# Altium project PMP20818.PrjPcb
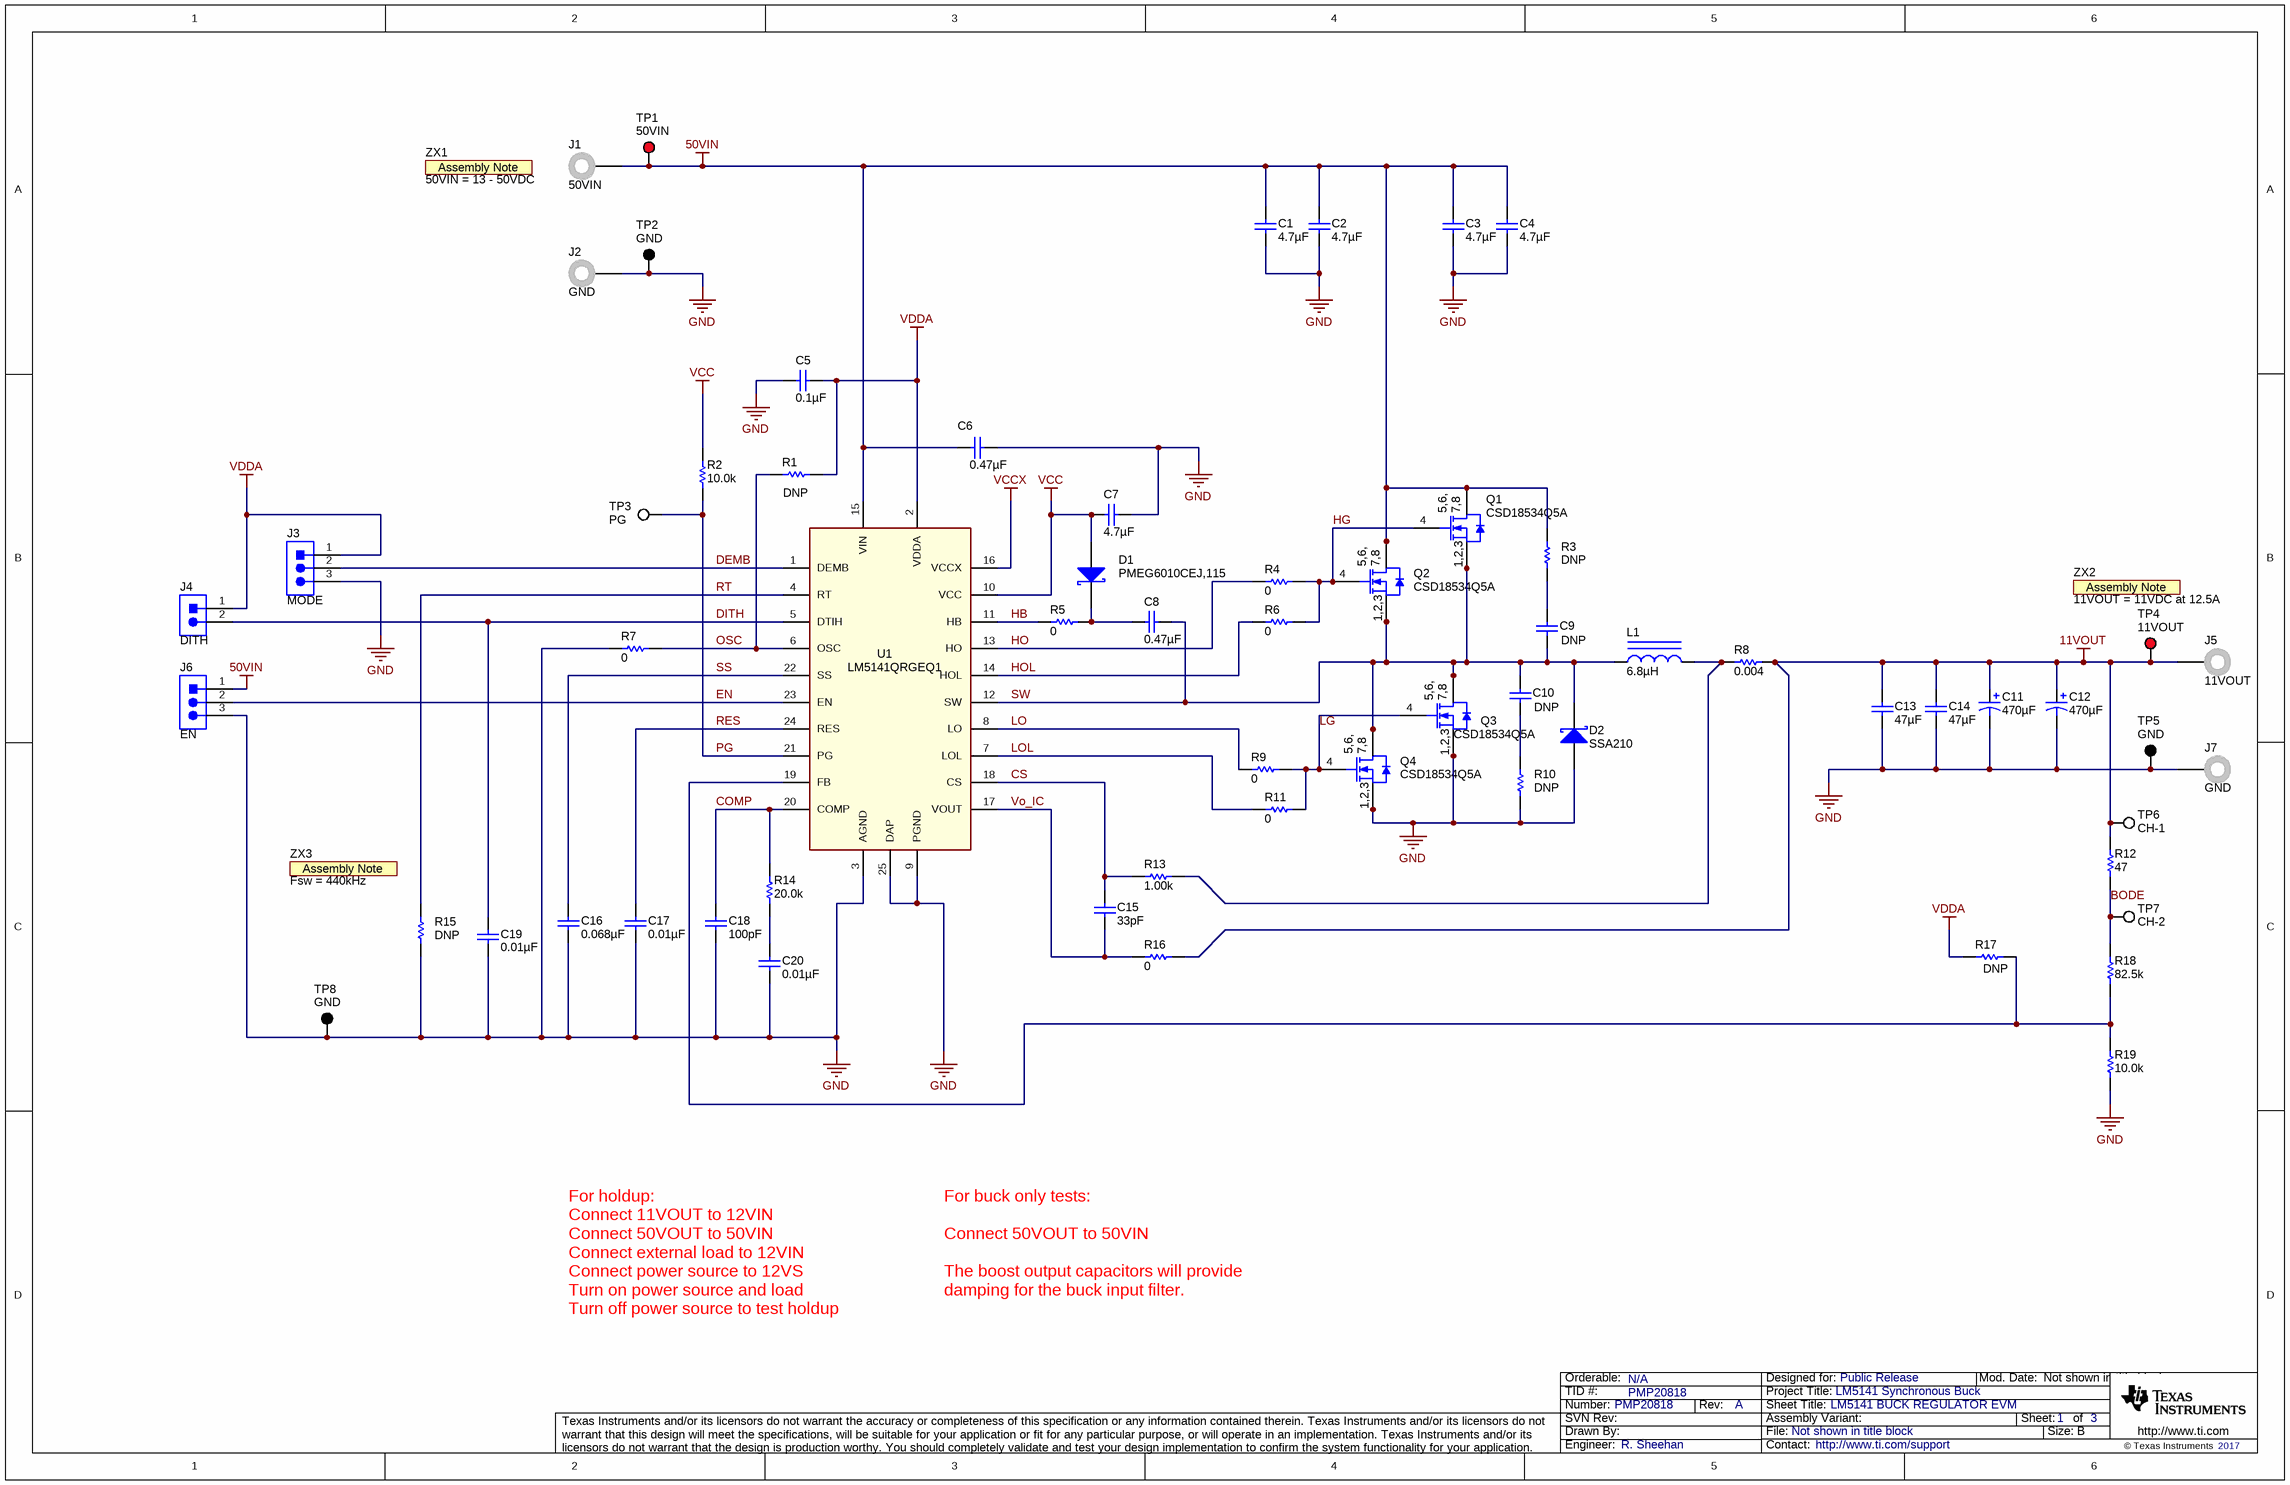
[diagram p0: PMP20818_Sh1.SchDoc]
CopyrightYear: 2017; EVM_Orderable: N/A; PCB_Layout: H. Kasparian; PCB_Rev: A; PRJ_Customer: Public Release; PRJ_Engineer: R. Sheehan; PRJ_Number: PMP20818; PRJ_Title: LM5141 Synchronous Buck; SCH_Rev: A; TechSupport: http://www.ti.com/support; TID: PMP20818
3 sheets, 134 parts. Net scope: global (net labels, ports and power ports of the same name join across sheets).
Board file: PMP20818.PcbDoc
Sheets:
  PMP20818_Sh1.SchDoc
  PMP20818_Sh2.SchDoc
  PMP20818_Sh3.SchDoc

## Sheet PMP20818_Sh1.SchDoc: LM5141 BUCK REGULATOR EVM
size 431 x 279 mm; Date: Not shown in title block; ApprovedBy: Not shown in title block; CheckedBy: Not shown in title block; Author: Not shown in title block; CompanyName: Not shown in title block; Engineer: Not shown in title block; Organization: Not shown in title block; Address1: Not shown in title block; Address2: Not shown in title block; Address3: Not shown in title block; Address4: Not shown in title block; DocumentNumber: 1; Revision: Use project parameter SCH_Rev; SheetNumber: 1; SheetTotal: 3; PageSetup: Record=PageOptions¦CenterHorizontal=True¦CenterVertical=True¦PrintScale=0.96¦XCorrection=1.00¦YCorrection=1.00¦PrintKind=0¦BorderSize=5000000¦LeftOffset=0¦BottomOffset=0¦Orientation=2¦PaperLength=1000¦PaperWidth=1000¦Scale=100¦PaperSource=15¦PrintQuality=-3¦MediaType=1¦DitherType=10¦PrintScaleMode=1¦PaperKind=11x17¦PaperIndex=17

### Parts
C1  ValueDisplayed: 4.7µF  [1206_190]  (hidden comment: UMK316AB7475KL-T)
C2  ValueDisplayed: 4.7µF  [1206_190]  (hidden comment: UMK316AB7475KL-T)
C3  ValueDisplayed: 4.7µF  [1206_190]  (hidden comment: UMK316AB7475KL-T)
C4  ValueDisplayed: 4.7µF  [1206_190]  (hidden comment: UMK316AB7475KL-T)
C5  ValueDisplayed: 0.1µF  [0603]  (hidden comment: C0603C104K5RACTU)
C6  ValueDisplayed: 0.47µF  [0805L]  (hidden comment: GRM21BR72A474KA73L)
C7  ValueDisplayed: 4.7µF  [0603]  (hidden comment: GRM188R61C475KAAJ)
C8  ValueDisplayed: 0.47µF  [0603]  (hidden comment: CGA3E3X7R1H474K080AB)
C9  DNP  [0603]
C10  DNP  [0603]
C11  ValueDisplayed: 470µF  [CAPSMT_62_JC0]  (hidden comment: 16SVPE470M)
C12  ValueDisplayed: 470µF  [CAPSMT_62_JC0]  (hidden comment: 16SVPE470M)
C13  ValueDisplayed: 47µF  [2220_250]  (hidden comment: CGA9N3X7R1C476M230KB)
C14  ValueDisplayed: 47µF  [2220_250]  (hidden comment: CGA9N3X7R1C476M230KB)
C15  ValueDisplayed: 33pF  [0603]  (hidden comment: 06035A330JAT2A)
C16  ValueDisplayed: 0.068µF  [0603]  (hidden comment: GRM188R71E683KA01D)
C17  ValueDisplayed: 0.01µF  [0603]  (hidden comment: C1608X7R2A103M)
C18  ValueDisplayed: 100pF  [0603]  (hidden comment: GRM1885C1H101JA01D)
C19  ValueDisplayed: 0.01µF  [0603]  (hidden comment: C1608X7R2A103M)
C20  ValueDisplayed: 0.01µF  [0603]  (hidden comment: GRM188R71E103KA01D)
D1  PMEG6010CEJ,115  [SOD-323F]
D2  SSA210  [SMA]
J1  50VIN  [Keystone_575-4]
J2  GND  [Keystone_575-4]
J3  MODE  [WURTH_61300311121]
J4  DITH  [WURTH_61300211121]
J5  11VOUT  [Keystone_575-4]
J6  EN  [WURTH_61300311121]
J7  GND  [Keystone_575-4]
L1  ValueDisplayed: 6.8µH  [XAL1510]  (hidden comment: XAL1510-682MEB)
Q1  CSD18534Q5A  [DQJ0008A]
Q2  CSD18534Q5A  [DQJ0008A]
Q3  CSD18534Q5A  [DQJ0008A]
Q4  CSD18534Q5A  [DQJ0008A]
R1  DNP  [0603]
R2  ValueDisplayed: 10.0k  [0603]  (hidden comment: CRCW060310K0FKEA)
R3  DNP  [1206]
R4  ValueDisplayed: 0  [0603S]  (hidden comment: CRCW06030000Z0EA)
R5  ValueDisplayed: 0  [0603S]  (hidden comment: CRCW06030000Z0EA)
R6  ValueDisplayed: 0  [0603S]  (hidden comment: CRCW06030000Z0EA)
R7  ValueDisplayed: 0  [0603]  (hidden comment: CRCW06030000Z0EA)
R8  ValueDisplayed: 0.004  [2512_WIDE]  (hidden comment: KRL6432E-M-R004-F-T1)
R9  ValueDisplayed: 0  [0603S]  (hidden comment: CRCW06030000Z0EA)
R10  DNP  [1206]
R11  ValueDisplayed: 0  [0603S]  (hidden comment: CRCW06030000Z0EA)
R12  ValueDisplayed: 47  [0603]  (hidden comment: CRCW060347R0JNEA)
R13  ValueDisplayed: 1.00k  [0603]  (hidden comment: CRCW06031K00FKEA)
R14  ValueDisplayed: 20.0k  [0603]  (hidden comment: CRCW060320K0FKEA)
R15  DNP  [0603]
R16  ValueDisplayed: 0  [0603]  (hidden comment: CRCW06030000Z0EA)
R17  DNP  [0603]
R18  ValueDisplayed: 82.5k  [0603]  (hidden comment: CRCW060382K5FKEA)
R19  ValueDisplayed: 10.0k  [0603]  (hidden comment: CRCW060310K0FKEA)
TP1  50VIN  [Keystone5010]
TP2  GND  [Keystone5011]
TP3  PG  [Keystone5012]
TP4  11VOUT  [Keystone5010]
TP5  GND  [Keystone5011]
TP6  CH-1  [Keystone5012]
TP7  CH-2  [Keystone5012]
TP8  GND  [Keystone5011]
U1  LM5141QRGEQ1  [RGE0024H]
ZX1  50VIN = 13 - 50VDC  [AssemblyNote]  (no BOM)
ZX2  11VOUT = 11VDC at 12.5A  [AssemblyNote]  (no BOM)
ZX3  Fsw = 440kHz  [AssemblyNote]  (no BOM)

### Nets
11VOUT: C11.1(+) C12.1(+) C13.1 C14.1 J5.1 R8.2 R12.2 R16.2 TP4.1 TP6.1
50VIN: C1.1 C2.1 C3.1 C4.1 C6.2 J1.1 J6.1 Q1.5(D) Q1.6(D) Q1.7(D) Q1.8(D) Q1.9(D) Q2.5(D) Q2.6(D) Q2.7(D) Q2.8(D) Q2.9(D) R3.2 TP1.1 U1.15(VIN)
GND: C1.2 C2.2 C3.2 C4.2 C5.1 C6.1 C7.1 C11.2(-) C12.2(-) C13.2 C14.2 C16.2 C17.2 C18.2 C19.2 C20.2 D2.2(A) J2.1 J3.3 J6.3 J7.1 Q3.1(S) Q3.2(S) Q3.3(S) Q4.1(S) Q4.2(S) Q4.3(S) R7.2 R10.1 R15.1 R19.1 TP2.1 TP5.1 TP8.1 U1.3(AGND) U1.9(PGND) U1.25(DAP)
VCC: C7.2 D1.2(A) R2.1 U1.10(VCC)
VCCX: U1.16(VCCX)
VDDA: C5.2 J3.1 J4.1 R1.1 R17.1 U1.2(VDDA)
BODE: R12.1 R18.2 TP7.1
COMP: C18.1 R14.2 U1.20(COMP)
CS: C15.2 R13.1 U1.18(CS)
DEMB: J3.2 U1.1(DEMB)
DITH: C19.1 J4.2 U1.5(DTIH)
EN: J6.2 U1.23(EN)
HB: R5.1 U1.11(HB)
HG: Q1.4(G) Q2.4(G) R4.2 R6.1
HO: R4.1 U1.13(HO)
HOL: R6.2 U1.14(HOL)
LG: Q3.4(G) Q4.4(G) R9.2 R11.1
LO: R9.1 U1.8(LO)
LOL: R11.2 U1.7(LOL)
OSC: R1.2 R7.1 U1.6(OSC)
PG: R2.2 TP3.1 U1.21(PG)
RES: C17.1 U1.24(RES)
RT: R15.2 U1.4(RT)
SS: C16.1 U1.22(SS)
SW: C8.2 C9.2 C10.1 D2.1(K) L1.1 Q1.1(S) Q1.2(S) Q1.3(S) Q2.1(S) Q2.2(S) Q2.3(S) Q3.5(D) Q3.6(D) Q3.7(D) Q3.8(D) Q3.9(D) Q4.5(D) Q4.6(D) Q4.7(D) Q4.8(D) Q4.9(D) U1.12(SW)
Vo_IC: C15.1 R16.1 U1.17(VOUT)
NetC8_1: C8.1 D1.1(K) R5.2
NetC9_1: C9.1 R3.1
NetC10_2: C10.2 R10.2
NetC20_1: C20.1 R14.1
NetL1_2: L1.2 R8.1 R13.2
NetR17_2: R17.2 R18.1 R19.2 U1.19(FB)

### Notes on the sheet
- For holdup:
  Connect 11VOUT to 12VIN
  Connect 50VOUT to 50VIN
  Connect external load to 12VIN
  Connect power source to 12VS
  Turn on power source and load
  Turn off power source to test holdup
- For buck only tests:
  Connect 50VOUT to 50VIN
  The boost output capacitors will provide damping for the buck input filter.

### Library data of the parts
C1-C4 = UMK316AB7475KL-T: CAP, CERM, 4.7 µF, 50 V, +/- 10%, X7R, 1206_190; Manufacturer: Taiyo Yuden; Polarized: N; CompType: Capacitor; Value: 4.7uF; U/M: EA; Cap_F: 0.0000047; Tolerance_%: 10; Value1: Unknown; VDC_V: 50; Value2: 50V; TaMin_C: -55; TaMax_C: 125; Cap_Case: 1206; SizeArea_mm2: 5.12; SizeAreaWB_mm2: 10.92; SizeX_mm: 3.2; SizeY_mm: 1.6; SizeZ_mm: 1.9; AEC Category: Q200
C5 = C0603C104K5RACTU: CAP, CERM, 0.1 µF, 50 V, +/- 10%, X7R, 0603; Manufacturer: Kemet; Polarized: N; CompType: Capacitor; Value: 0.1uF; U/M: EA; Cap_F: 0.0000001; Tolerance_%: 10; Value1: Unknown; VDC_V: 50; Value2: 50V; TaMin_C: -55; TaMax_C: 125
C6 = GRM21BR72A474KA73L: CAP, CERM, 0.47 µF, 100 V, +/- 10%, X7R, 0805; Manufacturer: MuRata; Polarized: N; CompType: Capacitor; Value: 0.47uF; U/M: EA; Cap_F: 0.00000047; Tolerance_%: 10; Value1: Unknown; VDC_V: 100; Value2: 100V; TaMin_C: -55; TaMax_C: 125; Cap_Case: 0805
C7 = GRM188R61C475KAAJ: CAP, CERM, 4.7 µF, 16 V, +/- 10%, X5R, 0603; Manufacturer: MuRata; Polarized: N; CompType: Capacitor; Value: 4.7uF; U/M: EA; Cap_F: 0.0000047; Tolerance_%: 10; Value1: Unknown; VDC_V: 16; Value2: 16V; TaMin_C: -55; TaMax_C: 85
C8 = CGA3E3X7R1H474K080AB: CAP, CERM, 0.47 µF, 50 V, +/- 10%, X7R, AEC-Q200 Grade 1, 0603; Manufacturer: TDK; Polarized: N; CompType: Capacitor; Value: 0.47uF; U/M: EA; Cap_F: 0.00000047; Tolerance_%: 10; ESR_ohm: 0.01064; Value1: 0.01064 ohm; VDC_V: 50; Value2: 50V; IRMS_A: 1.59966; TaMin_C: -55; TaMax_C: 125; SizeArea_mm2: 1.28; SizeAreaWB_mm2: 4.68; SizeX_mm: 1.6; SizeY_mm: 0.8; SizeZ_mm: 1; AEC Category: Q200; AEC Qualified: Y
C9 C10 = GRM1885C2A102JA01D: CAP, CERM, 1000 pF, 100 V, +/- 5%, C0G/NP0, 0603; Manufacturer: MuRata; Polarized: N; CompType: Capacitor; Value: 1000pF; U/M: EA; Cap_F: 0.000000001; Tolerance_%: 5; Value1: Unknown; VDC_V: 100; Value2: 100V; TaMin_C: -55; TaMax_C: 125
C11 C12 = 16SVPE470M: CAP, Aluminum Polymer, 470 µF, 16 V, +/- 20%, 0.01 ohm, JC0 SMD; Manufacturer: Panasonic; Polarized: Y; CompType: Capacitor; Value: 470uF; U/M: EA; Cap_F: 0.00047; Tolerance_%: 20; VDC_V: 16; Value2: 16V; ESR_ohm: 0.01; IRMS_A: 6.1; TaMin_C: -55; TaMax_C: 105; AEC Category: Q200; SizeAreaWB_mm2: 156.25; SizeArea_mm2: 110.25; SizeX_mm: 10.5; SizeZ_mm: 12.5
C13 C14 = CGA9N3X7R1C476M230KB: CAP, CERM, 47 µF, 16 V, +/- 20%, X7R, AEC-Q200 Grade 1,; Manufacturer: TDK; Polarized: N; CompType: Capacitor; Value: 47uF; U/M: EA; Cap_F: 0.000047; Tolerance_%: 20; ESR_ohm: 0.003162; Value1: 0.003162 ohm; VDC_V: 16; Value2: 16V; IRMS_A: 5.13436; TaMin_C: -55; TaMax_C: 125; SizeArea_mm2: 28.5; SizeAreaWB_mm2: 53.9; SizeX_mm: 5.7; SizeY_mm: 5; SizeZ_mm: 2.5; AEC Category: Q200; AEC Qualified: Y; AEC Grade: 1
C15 = 06035A330JAT2A: CAP, CERM, 33 pF, 50 V, +/- 5%, C0G/NP0, 0603; Manufacturer: AVX; Polarized: N; CompType: Capacitor; Value: 33pF; U/M: EA; Cap_F: 0.000000000033; Tolerance_%: 5; ESR_ohm: 0.209; Value1: 0.209 ohm; VDC_V: 50; Value2: 50V; TaMin_C: -55; TaMax_C: 125
C16 = GRM188R71E683KA01D: CAP, CERM, 0.068 µF, 25 V, +/- 10%, X7R, 0603; Manufacturer: MuRata; Polarized: N; CompType: Capacitor; Value: 0.068uF; U/M: EA; Cap_F: 0.000000068; Tolerance_%: 10; Value1: Unknown; VDC_V: 25; Value2: 25V; TaMin_C: -55; TaMax_C: 125
C17 C19 = C1608X7R2A103M: CAP, CERM, 0.01 µF, 100 V, +/- 20%, X7R, 0603; Manufacturer: TDK; Polarized: N; CompType: Capacitor; Value: 0.01uF; U/M: EA; Cap_F: 0.00000001; Tolerance_%: 20; ESR_ohm: 0.0661; Value1: 0.0661 ohm; VDC_V: 100; Value2: 100V; TaMin_C: -55; TaMax_C: 125
C18 = GRM1885C1H101JA01D: CAP, CERM, 100 pF, 50 V, +/- 5%, C0G/NP0, 0603; Manufacturer: MuRata; Polarized: N; CompType: Capacitor; Value: 100pF; U/M: EA; Cap_F: 0.0000000001; Tolerance_%: 5; Value1: Unknown; VDC_V: 50; Value2: 50V; TaMin_C: -55; TaMax_C: 125; SizeArea_mm2: 1.28; SizeAreaWB_mm2: 4.68; SizeX_mm: 1.6; SizeY_mm: 0.8; SizeZ_mm: 1; AEC Category: Q200
C20 = GRM188R71E103KA01D: CAP, CERM, 0.01 µF, 25 V, +/- 10%, X7R, 0603; Manufacturer: MuRata; Polarized: N; CompType: Capacitor; Value: 0.01uF; U/M: EA; Cap_F: 0.00000001; Tolerance_%: 10; Value1: Unknown; VDC_V: 25; Value2: 25V; TaMin_C: -55; TaMax_C: 125; SizeArea_mm2: 1.28; SizeAreaWB_mm2: 4.68; SizeX_mm: 1.6; SizeY_mm: 0.8; SizeZ_mm: 1; AEC Category: Q200
D1 = PMEG6010CEJ,115: Diode, Schottky, 60 V, 1 A, SOD-323F; Manufacturer: NXP Semiconductor; U/M: EA; Vf_V: 0.66; Value: 60V; Value1: 1A; Value2: 0.66V; Io_A: 1; Vr_V: 60; TJmax_C: 150
D2 = SSA210: Diode, Schottky, 100 V, 2 A, AEC-Q101, SMA; Manufacturer: Fairchild Semiconductor; U/M: EA; Vf_V: 0.8; Value: 100V; Value1: 2A; Value2: 0.8V; Io_A: 2; Vr_V: 100; TJmax_C: 175; SizeAreaWB_mm2: 37.3428; SizeArea_mm2: 16.3228; SizeX_mm: 5.59; SizeY_mm: 2.92; SizeZ_mm: 2.87; AEC Category: Q101; AEC Qualified: Y
J1 J2 J5 J7 = 575-4: Standard Banana Jack, Uninsulated, 5.5mm; Manufacturer: Keystone; CompType: Connector
J3 J6 = 61300311121: Header, 2.54 mm, 3x1, Gold, TH; Manufacturer: Wurth Elektronik; SymbolCreator: a0799628
J4 = 61300211121: Header, 2.54 mm, 2x1, Gold, TH; Manufacturer: Wurth Elektronik; SymbolCreator: a0412235
L1 = XAL1510-682MEB: Inductor, Shielded, Composite, 6.8 µH, 26 A, 0.00417 ohm, SMD; Manufacturer: Coilcraft; Value: 6.8uH; Ind_H: 6.8E-6; Imax_A: 26; Irms: 26A @ 40C rise; Isat: 36A @ 30% inductance drop; Value2: 26A; AEC Category: Q200; SizeAreaWB_mm2: 320.16; SizeArea_mm2: 252.56; SizeX_mm: 16.4; SizeY_mm: 15.4; SizeZ_mm: 10
Q1-Q4 = CSD18534Q5A: MOSFET, N-CH, 60 V, 50 A, DQJ0008A (VSONP-8); Manufacturer: Texas Instruments; Alternate Manufacturer: None; U/M: EA; VdsMax_V: 60; ChType: N; Value: 60V; Value1: 0.0098 ohm; Rdson45_ohm: 0.0098; Value2: 22 nC; QgTyp_nC: 22; Vgs_V: 2.3; IdsMax_A: 50; SizeAreaWB_mm2: 55.2; SizeArea_mm2: 29.4; SizeX_mm: 6; SizeY_mm: 4.9; SizeZ_mm: 1.1; AEC Category: Q101
R1 R6 R7 R16 = CRCW06030000Z0EA: RES, 0, 5%, 0.1 W, 0603; Manufacturer: Vishay-Dale; CompType: Resistor; Value: 0; Value_Code: 0000; Tolerance_%: 5; Power_W: 0.1; Value2: 0.1W; VDC_V: 75; TempCo: 200 ppm/C; EIA_Code: E24; U/M: EA
R2 = CRCW060310K0FKEA: RES, 10.0 k, 1%, 0.1 W, 0603; Manufacturer: Vishay-Dale; CompType: Resistor; Value: 10.0k; Res_ohm: 10000; Value_Code: 10k0; Tolerance_%: 1; Power_W: 0.1; Value2: 0.1W; VDC_V: 75; TempCo: 100 ppm/C; EIA_Code: E96; U/M: EA
R3 R10 = CRM1206-JW-1R0ELF: RES, 1.0, 5%, 0.5 W, 1206; Manufacturer: Bourns; CompType: Resistor; Value: 1.0; Res_ohm: 1; Value_Code: 1R00; Tolerance_%: 5; Power_W: 0.5; Value2: 0.5W; TempCo: 150 ppm/C; EIA_Code: E24; U/M: EA
R4 R5 R9 R11 = CRCW06030000Z0EA: RES, 0, 5%, 0.1 W, 0603; Manufacturer: Vishay-Dale; CompType: Resistor; Value: 0; Value_Code: 0000; Tolerance_%: 5; Power_W: 0.1; Value2: 0.1W; VDC_V: 75; TempCo: 200 ppm/C; EIA_Code: E24; U/M: EA; SizeArea_mm2: 1.28; SizeX_mm: 1.6; SizeY_mm: 0.8; SizeZ_mm: 1; AEC Category: Q200
R8 = KRL6432E-M-R007-F-T1: RES, 0.004, 1%, 3 W, 2512 WIDE; Manufacturer: Susumu Co Ltd; CompType: Resistor; Value: 0.004; U/M: EA; Value_Code: 4L000; Tolerance_%: 1; Power_W: 3; Value2: 3W; TempCo: 50 ppm/C; SizeArea_mm2: 20.16; SizeAreaWB_mm2: 43.16; SizeX_mm: 3.2; SizeY_mm: 6.3; SizeZ_mm: 0.7; EIA_Code: E96; AEC Category: Q200
R12 = CRCW060347R0JNEA: RES, 47, 5%, 0.1 W, 0603; Manufacturer: Vishay-Dale; CompType: Resistor; Value: 47; Value_Code: 47R0; Tolerance_%: 5; Power_W: 0.1; Value2: 0.1W; VDC_V: 75; TempCo: 200 ppm/C; EIA_Code: E24; U/M: EA; SizeArea_mm2: 1.28; SizeX_mm: 1.6; SizeY_mm: 0.8; SizeZ_mm: 1; AEC Category: Q200
R13 = CRCW06031K00FKEA: RES, 1.00 k, 1%, 0.1 W, 0603; Manufacturer: Vishay-Dale; CompType: Resistor; Value: 1.00k; Res_ohm: 1000; Value_Code: 1k00; Tolerance_%: 1; Power_W: 0.1; Value2: 0.1W; VDC_V: 75; TempCo: 100 ppm/C; EIA_Code: E96; U/M: EA; SizeArea_mm2: 1.28; SizeX_mm: 1.6; SizeY_mm: 0.8; AEC Category: Q200
R14 = CRCW060320K0FKEA: RES, 20.0 k, 1%, 0.1 W, 0603; Manufacturer: Vishay-Dale; CompType: Resistor; Value: 20.0k; Res_ohm: 20000; Value_Code: 20k0; Tolerance_%: 1; Power_W: 0.1; Value2: 0.1W; VDC_V: 75; TempCo: 100 ppm/C; EIA_Code: E96; U/M: EA; SizeArea_mm2: 1.28; SizeX_mm: 1.6; SizeY_mm: 0.8; AEC Category: Q200
R15 = CRCW060349K9FKEA: RES, 49.9 k, 1%, 0.1 W, 0603; Manufacturer: Vishay-Dale; CompType: Resistor; Value: 49.9k; Res_ohm: 49900; Value_Code: 49k9; Tolerance_%: 1; Power_W: 0.1; Value2: 0.1W; VDC_V: 75; TempCo: 100 ppm/C; SizeArea_mm2: 1.28; SizeX_mm: 1.6; SizeY_mm: 0.8; EIA_Code: E96; U/M: EA; AEC Category: Q200
R17 = CRCW06030000Z0EA: RES, 0, 5%, 0.1 W, 0603; Manufacturer: Vishay-Dale; CompType: Resistor; Value: 0; Value_Code: 0000; Tolerance_%: 5; Power_W: 0.1; Value2: 0.1W; VDC_V: 75; TempCo: 200 ppm/C; SizeArea_mm2: 1.28; SizeX_mm: 1.6; SizeY_mm: 0.8; SizeZ_mm: 1; EIA_Code: E24; U/M: EA; AEC Category: Q200
R18 = CRCW060382K5FKEA: RES, 82.5 k, 1%, 0.1 W, 0603; Manufacturer: Vishay-Dale; CompType: Resistor; Value: 82.5k; Res_ohm: 82500; Value_Code: 82k5; Tolerance_%: 1; Power_W: 0.1; Value2: 0.1W; VDC_V: 75; TempCo: 100 ppm/C; EIA_Code: E96; U/M: EA; AEC Category: Q200; SizeArea_mm2: 1.28; SizeX_mm: 1.6; SizeY_mm: 0.8
R19 = CRCW060310K0FKEA: RES, 10.0 k, 1%, 0.1 W, 0603; Manufacturer: Vishay-Dale; CompType: Resistor; Value: 10.0k; Res_ohm: 10000; Value_Code: 10k0; Tolerance_%: 1; Power_W: 0.1; Value2: 0.1W; VDC_V: 75; TempCo: 100 ppm/C; EIA_Code: E96; U/M: EA; SizeArea_mm2: 1.28; SizeX_mm: 1.6; SizeY_mm: 0.8; AEC Category: Q200
TP1 TP4 = 5010: Test Point, Multipurpose, Red, TH; Manufacturer: Keystone; CompType: Test Point Loop; ContactFinish: Silver
TP2 TP5 TP8 = 5011: Test Point, Multipurpose, Black, TH; Manufacturer: Keystone; CompType: Test Point Loop; ContactFinish: Silver
TP3 TP6 TP7 = 5012: Test Point, Multipurpose, White, TH; Manufacturer: Keystone; CompType: Test Point Loop; ContactFinish: Silver
U1 = LM5141QRGEQ1: IC, PWM, Buck Controller, w/ Dither; Manufacturer: Texas Instruments; SymbolVersion: use current date i.e. 2008-05-20; SymbolCreator: Use a-id; U/M: EA, IN, or GM
ZX1-ZX3 = AssemblyNote: This Assembly Note will show in the PcbDoc and associated outputs; SymbolCreator: codlsc

## Sheet PMP20818_Sh2.SchDoc: LM5141 BUCK REGULATOR EVM
size 431 x 279 mm; Date: Not shown in title block; ApprovedBy: Not shown in title block; CheckedBy: Not shown in title block; Author: Not shown in title block; CompanyName: Not shown in title block; Engineer: Not shown in title block; Organization: Not shown in title block; Address1: Not shown in title block; Address2: Not shown in title block; Address3: Not shown in title block; Address4: Not shown in title block; DocumentNumber: 2; Revision: Use project parameter SCH_Rev; SheetNumber: 2; SheetTotal: 3; PageSetup: Record=PageOptions¦CenterHorizontal=True¦CenterVertical=True¦PrintScale=0.96¦XCorrection=1.00¦YCorrection=1.00¦PrintKind=0¦BorderSize=5000000¦LeftOffset=0¦BottomOffset=0¦Orientation=2¦PaperLength=1000¦PaperWidth=1000¦Scale=100¦PaperSource=15¦PrintQuality=-3¦MediaType=1¦DitherType=10¦PrintScaleMode=1¦PaperKind=11x17¦PaperIndex=17
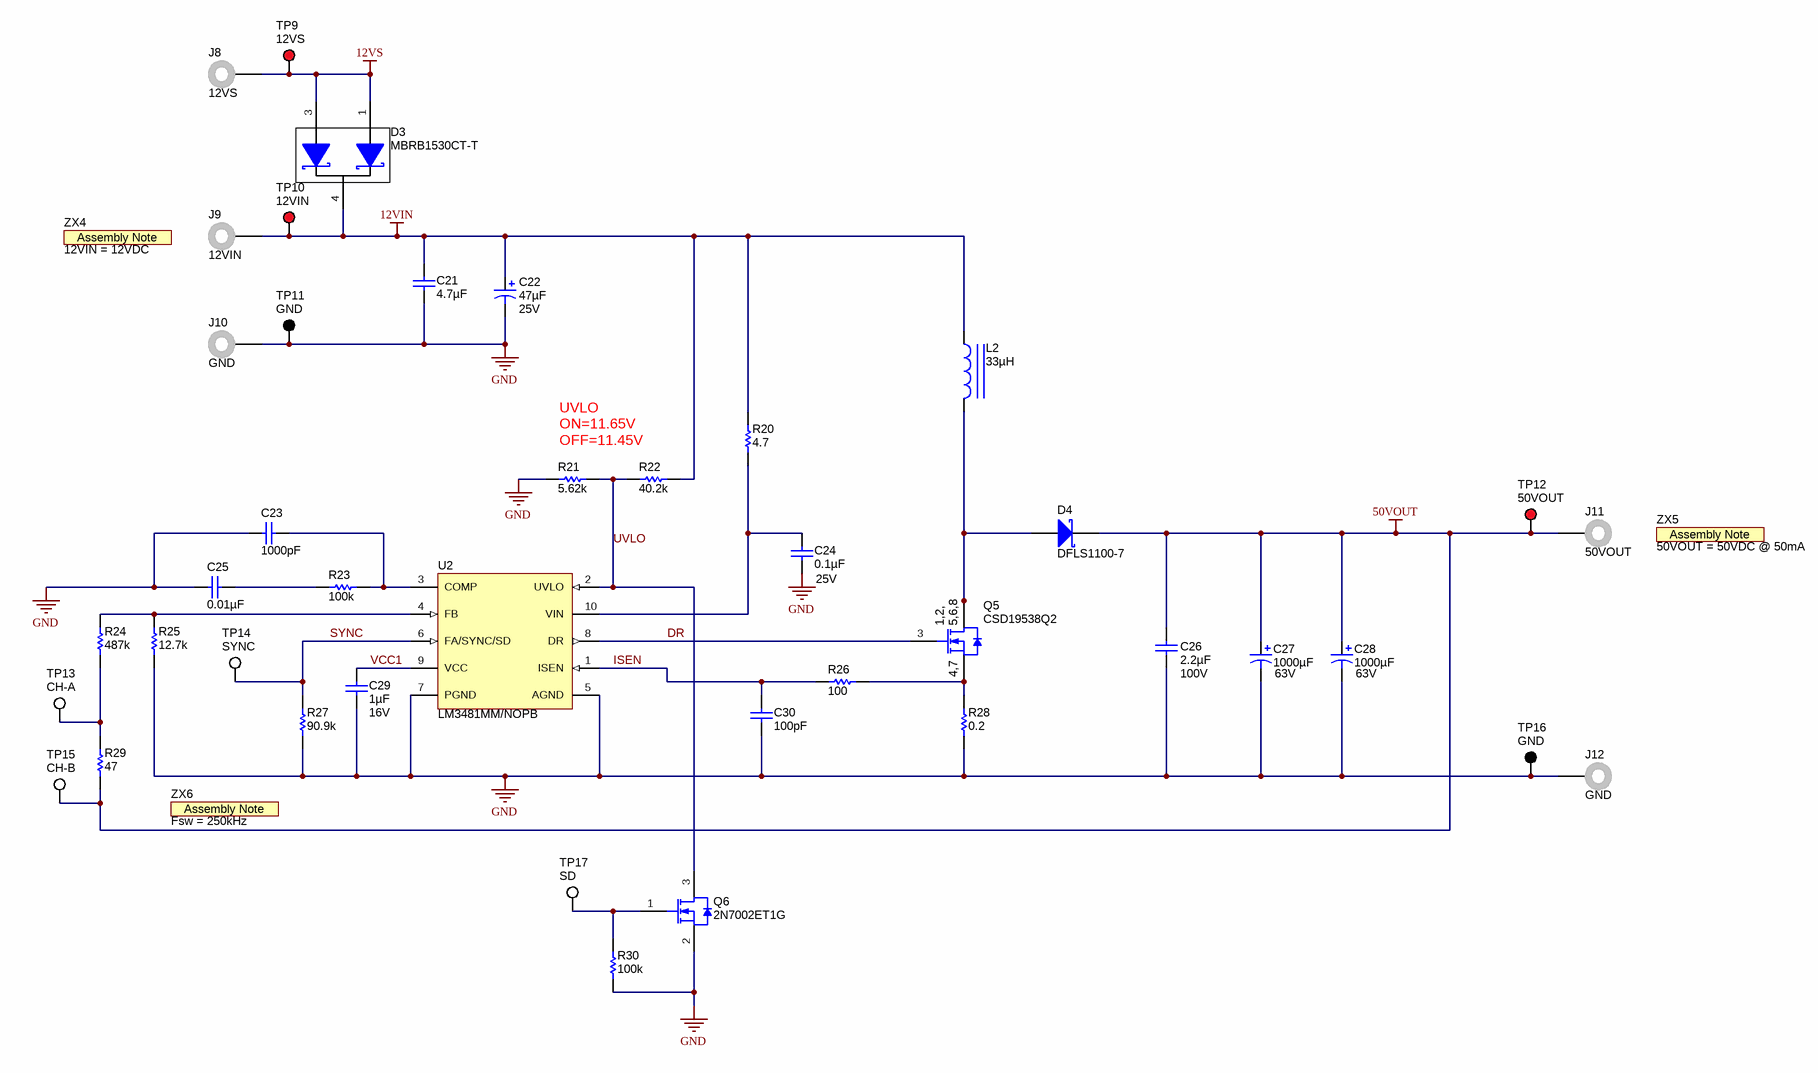
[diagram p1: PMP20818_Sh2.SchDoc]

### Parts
C21  ValueDisplayed: 4.7µF  [1206_180]  (hidden comment: GRM31CR71E475KA88L)
C22  ValueDisplayed: 47µF  Value2: 25V  [SM_RADIAL_6.3AMM]  (hidden comment: UUD1E470MCL1GS)
C23  ValueDisplayed: 1000pF  [0603]  (hidden comment: GRM188R71H102KA01D)
C24  ValueDisplayed: 0.1µF  Value2: 25V  [0603]  (hidden comment: 06033C104JAT2A)
C25  ValueDisplayed: 0.01µF  [0603]  (hidden comment: GRM188R71H103KA01D)
C26  ValueDisplayed: 2.2µF  Value2: 100V  [1210]  (hidden comment: GRM32ER72A225KA35L)
C27  ValueDisplayed: 1000µF  Value2: 63V  [UPW_1600x3150]  (hidden comment: UPW1J102MHD)
C28  ValueDisplayed: 1000µF  Value2: 63V  [UPW_1600x3150]  (hidden comment: UPW1J102MHD)
C29  ValueDisplayed: 1µF  Value2: 16V  [0603]  (hidden comment: C1608X7R1C105K)
C30  ValueDisplayed: 100pF  [0603]  (hidden comment: GRM1885C1H101JA01D)
D3  MBRB1530CT-T  [DDPAK]
D4  DFLS1100-7  [PowerDI123]
J8  12VS  [Keystone_575-4]
J9  12VIN  [Keystone_575-4]
J10  GND  [Keystone_575-4]
J11  50VOUT  [Keystone_575-4]
J12  GND  [Keystone_575-4]
L2  ValueDisplayed: 33µH  [LPS4018]  (hidden comment: LPS4018-333MLB)
Q5  CSD19538Q2  [DQK0006C]
Q6  2N7002ET1G  [SOT-23]
R20  ValueDisplayed: 4.7  [0603]  (hidden comment: CRCW06034R70JNEA)
R21  ValueDisplayed: 5.62k  [0603]  (hidden comment: CRCW06035K62FKEA)
R22  ValueDisplayed: 40.2k  [0603]  (hidden comment: CRCW060340K2FKEA)
R23  ValueDisplayed: 100k  [0603]  (hidden comment: CRCW0603100KFKEA)
R24  ValueDisplayed: 487k  [0603]  (hidden comment: CRCW0603487KFKEA)
R25  ValueDisplayed: 12.7k  [0603]  (hidden comment: CRCW060312K7FKEA)
R26  ValueDisplayed: 100  [0603]  (hidden comment: CRCW0603100RFKEA)
R27  ValueDisplayed: 90.9k  [0603]  (hidden comment: CRCW060390K9FKEA)
R28  ValueDisplayed: 0.2  [1206]  (hidden comment: CSR1206FKR200)
R29  ValueDisplayed: 47  [0603]  (hidden comment: CRCW060347R0JNEA)
R30  ValueDisplayed: 100k  [0603]  (hidden comment: CRCW0603100KFKEA)
TP9  12VS  [Keystone5010]
TP10  12VIN  [Keystone5010]
TP11  GND  [Keystone5011]
TP12  50VOUT  [Keystone5010]
TP13  CH-A  [Keystone5012]
TP14  SYNC  [Keystone5012]
TP15  CH-B  [Keystone5012]
TP16  GND  [Keystone5011]
TP17  SD  [Keystone5012]
U2  LM3481MM/NOPB  [MUB10A_N]
ZX4  12VIN = 12VDC  [AssemblyNote]  (no BOM)
ZX5  50VOUT = 50VDC @ 50mA  [AssemblyNote]  (no BOM)
ZX6  Fsw = 250kHz  [AssemblyNote]  (no BOM)

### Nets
12VIN: C21.1 C22.1(+) D3.4(K) J9.1 L2.1 R20.2 R22.1 TP10.1
12VS: D3.1(A) D3.3(A) J8.1 TP9.1
50VOUT: C26.1 C27.1(+) C28.1(+) D4.1(K) J11.1 R29.1 TP12.1 TP15.1
GND: C21.2 C22.2(-) C23.2 C24.2 C25.2 C26.2 C27.2(-) C28.2(-) C29.2 C30.2 J10.1 J12.1 Q6.2(S) R21.2 R25.1 R27.2 R28.1 R30.1 TP11.1 TP16.1 U2.5(AGND) U2.7(PGND)
DR: Q5.3(G) U2.8(DR)
ISEN: C30.1 R26.1 U2.1(ISEN)
SYNC: R27.1 TP14.1 U2.6(FA/SYNC/SD)
UVLO: Q6.3(D) R21.1 R22.2 U2.2(UVLO)
VCC1: C29.1 U2.9(VCC)
NetC23_1: C23.1 R23.2 U2.3(COMP)
NetC24_1: C24.1 R20.1 U2.10(VIN)
NetC25_1: C25.1 R23.1
NetD4_2: D4.2(A) L2.2 Q5.1(D) Q5.2(D) Q5.5(D) Q5.6(D) Q5.8(D)
NetQ5_4: Q5.4(S) Q5.7(S) R26.2 R28.2
NetQ6_1: Q6.1(G) R30.2 TP17.1
NetR24_1: R24.1 R29.2 TP13.1
NetR24_2: R24.2 R25.2 U2.4(FB)

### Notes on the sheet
- UVLO
  ON=11.65V
  OFF=11.45V

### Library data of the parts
C21 = GRM31CR71E475KA88L: CAP, CERM, 4.7 µF, 25 V, +/- 10%, X7R, 1206; Manufacturer: MuRata; Polarized: N; CompType: Capacitor; Value: 4.7uF; U/M: EA; Cap_F: 0.0000047; Tolerance_%: 10; Value1: Unknown; VDC_V: 25; Value2: 25V; TaMin_C: -55; TaMax_C: 125; Cap_Case: 1206; SizeArea_mm2: 5.12; SizeAreaWB_mm2: 10.92; SizeX_mm: 3.2; SizeY_mm: 1.6; SizeZ_mm: 1.8; AEC Category: Q200
C22 = UUD1E470MCL1GS: CAP, AL, 47 µF, 25 V, +/- 20%, 0.44 ohm, SMD; Manufacturer: Nichicon; Polarized: Y; CompType: Capacitor; Value: 47uF; U/M: EA; Cap_F: 0.000047; Tolerance_%: 20; VDC_V: 25; ESR_ohm: 0.44; IRMS_A: 0.23; TaMin_C: -55; TaMax_C: 105; Cap_Case: 6.3x5.8; SizeAreaWB_mm2: 79.98; SizeArea_mm2: 48.18; SizeX_mm: 7.3; SizeY_mm: 6.6; SizeZ_mm: 6; AEC Category: Q200
C23 = GRM188R71H102KA01D: CAP, CERM, 1000 pF, 50 V, +/- 10%, X7R, 0603; Manufacturer: MuRata; Polarized: N; CompType: Capacitor; Value: 1000pF; U/M: EA; Cap_F: 0.000000001; Tolerance_%: 10; Value1: Unknown; VDC_V: 50; Value2: 50V; TaMin_C: -55; TaMax_C: 125; SizeArea_mm2: 1.28; SizeAreaWB_mm2: 4.68; SizeX_mm: 1.6; SizeY_mm: 0.8; SizeZ_mm: 1; AEC Category: Q200
C24 = 06033C104JAT2A: CAP, CERM, 0.1 µF, 25 V, +/- 5%, X7R, 0603; Manufacturer: AVX; Polarized: N; CompType: Capacitor; Value: 0.1uF; U/M: EA; Cap_F: 0.0000001; Tolerance_%: 5; ESR_ohm: 0.05; Value1: 0.05 ohm; VDC_V: 25; TaMin_C: -55; TaMax_C: 125
C25 = GRM188R71H103KA01D: CAP, CERM, 0.01 µF, 50 V, +/- 10%, X7R, 0603; Manufacturer: MuRata; Polarized: N; CompType: Capacitor; Value: 0.01uF; U/M: EA; Cap_F: 0.00000001; Tolerance_%: 10; Value1: Unknown; VDC_V: 50; Value2: 50V; TaMin_C: -55; TaMax_C: 125; SizeArea_mm2: 1.28; SizeAreaWB_mm2: 4.68; SizeX_mm: 1.6; SizeY_mm: 0.8; SizeZ_mm: 1; AEC Category: Q200
C26 = GRM32ER72A225KA35L: CAP, CERM, 2.2 µF, 100 V, +/- 10%, X7R, 1210; Manufacturer: MuRata; Polarized: N; CompType: Capacitor; Value: 2.2uF; U/M: EA; Cap_F: 0.0000022; Tolerance_%: 10; ESR_ohm: 0.007; Value1: 0.007 ohm; VDC_V: 100; IRMS_A: 4.4; TaMin_C: -55; TaMax_C: 125
C27 C28 = UPW1J102MHD: CAP, AL, 1000 µF, 63 V, +/- 20%, 0.043 ohm, TH; Manufacturer: Nichicon; Polarized: Y; CompType: Capacitor; Value: 1000uF; U/M: EA; Cap_F: 0.001; Tolerance_%: 20; VDC_V: 63; ESR_ohm: 0.043; IRMS_A: 2.77; TaMin_C: -55; TaMax_C: 105; Cap_Case: 16x31.5mm; SizeAreaWB_mm2: 324; SizeArea_mm2: 256; SizeX_mm: 16; SizeZ_mm: 33.5; AEC Category: Q200; AEC Qualified: N
C29 = C1608X7R1C105K: CAP, CERM, 1 µF, 16 V, +/- 10%, X7R, 0603; Manufacturer: TDK; Polarized: N; CompType: Capacitor; Value: 1uF; U/M: EA; Cap_F: 0.000001; Tolerance_%: 10; ESR_ohm: 0.0057; Value1: 0.0057 ohm; VDC_V: 16; TaMin_C: -55; TaMax_C: 125
C30 = GRM1885C1H101JA01D: as C18 on sheet PMP20818_Sh1
D3 = MBRB1530CT-T: Diode, Schottky, 30 V, 15 A, DDPAK; Manufacturer: Diodes Inc.; U/M: EA; Vf_V: 0.65; Value: 30V; Value1: 15A; Value2: 0.65V; Io_A: 15; Vr_V: 30; TJmax_C: 150; RJC_CperW: 3; SizeAreaWB_mm2: 209.6992; SizeArea_mm2: 154.8892; SizeX_mm: 15.245; SizeY_mm: 10.16; SizeZ_mm: 4.445; AEC Category: Q101
D4 = DFLS1100-7: Diode, Schottky, 100 V, 1 A, PowerDI123; Manufacturer: Diodes Inc.; U/M: EA; Vf_V: 0.77; Value: 100V; Value1: 1A; Value2: 0.77V; Io_A: 1; Vr_V: 100; TJmax_C: 175; RJC_CperW: 7; SizeAreaWB_mm2: 13.066; SizeArea_mm2: 6.586; SizeX_mm: 3.7; SizeY_mm: 1.78; SizeZ_mm: 0.98; AEC Category: Q101
J8-J12 = 575-4: as J1 on sheet PMP20818_Sh1
L2 = LPS4018-333MLB: Inductor, Shielded Drum Core, Ferrite, 33 µH, 0.68 A, 0.42 ohm, SMD; Manufacturer: Coilcraft; Value: 33uH; Ind_H: 33.0E-6; Imax_A: 0.68; Irms: 0.8A @ 40C rise; Isat: 0.68A @ 30% inductance drop; DCR_ohm: 0.42; Value2: 0.68A; SizeAreaWB_mm2: 24.01; SizeArea_mm2: 15.21; SizeX_mm: 3.9; SizeZ_mm: 1.7; AEC Category: Q200
Q5 = CSD19538Q2: MOSFET, N-CH, 100 V, 4.5 A, DQK0006C (WSON-6); Manufacturer: Texas Instruments; Alternate Manufacturer: None; U/M: EA; ChType: N; Value: 100V; VdsMax_V: 100; Value1: ? ohm; Value2: ? nC; Vgs_V: 20; IdsMax_A: 4.5; SizeAreaWB_mm2: 9; SizeArea_mm2: 4; SizeX_mm: 2; SizeZ_mm: 0.8; AEC Category: Q101
Q6 = 2N7002ET1G: MOSFET, N-CH, 60 V, 0.26 A, SOT-23; Manufacturer: ON Semiconductor; Alternate Manufacturer: None; U/M: EA; ChType: N; Value: 60V; VdsMax_V: 60; Value1: 3 ohm; Rdson45_ohm: 3; Value2: 0.81 nC; QgTyp_nC: 0.81; Vgs_V: 20; IdsMax_A: 0.26
R20 = CRCW06034R70JNEA: RES, 4.7, 5%, 0.1 W, 0603; Manufacturer: Vishay-Dale; CompType: Resistor; Value: 4.7; Value_Code: 4R70; Tolerance_%: 5; Power_W: 0.1; Value2: 0.1W; VDC_V: 75; TempCo: 200 ppm/C; EIA_Code: E24; U/M: EA
R21 = CRCW06035K62FKEA: RES, 5.62 k, 1%, 0.1 W, 0603; Manufacturer: Vishay-Dale; CompType: Resistor; Value: 5.62k; Res_ohm: 5620; Value_Code: 5k62; Tolerance_%: 1; Power_W: 0.1; Value2: 0.1W; VDC_V: 75; TempCo: 100 ppm/C; EIA_Code: E96; U/M: EA; SizeArea_mm2: 1.28; SizeX_mm: 1.6; SizeY_mm: 0.8; AEC Category: Q200
R22 = CRCW060340K2FKEA: RES, 40.2 k, 1%, 0.1 W, 0603; Manufacturer: Vishay-Dale; CompType: Resistor; Value: 40.2k; Res_ohm: 40200; Value_Code: 40k2; Tolerance_%: 1; Power_W: 0.1; Value2: 0.1W; VDC_V: 75; TempCo: 100 ppm/C; EIA_Code: E96; U/M: EA
R23 = CRCW0603100KFKEA: RES, 100 k, 1%, 0.1 W, 0603; Manufacturer: Vishay-Dale; CompType: Resistor; Value: 100k; Res_ohm: 100000; Tolerance_%: 1; Power_W: 0.1; Value2: 0.1W; VDC_V: 75; TempCo: 100 ppm/C; EIA_Code: E96; U/M: EA; SizeArea_mm2: 1.28; SizeX_mm: 1.6; SizeY_mm: 0.8; AEC Category: Q200
R24 = CRCW0603487KFKEA: RES, 487 k, 1%, 0.1 W, 0603; Manufacturer: Vishay-Dale; CompType: Resistor; Value: 487k; Res_ohm: 487000; Tolerance_%: 1; Power_W: 0.1; Value2: 0.1W; VDC_V: 75; TempCo: 100 ppm/C; EIA_Code: E96; U/M: EA; SizeArea_mm2: 1.28; SizeX_mm: 1.6; SizeY_mm: 0.8; AEC Category: Q200
R25 = CRCW060312K7FKEA: RES, 12.7 k, 1%, 0.1 W, 0603; Manufacturer: Vishay-Dale; CompType: Resistor; Value: 12.7k; Res_ohm: 12700; Value_Code: 12k7; Tolerance_%: 1; Power_W: 0.1; Value2: 0.1W; VDC_V: 75; TempCo: 100 ppm/C; EIA_Code: E96; U/M: EA; SizeArea_mm2: 1.28; SizeX_mm: 1.6; SizeY_mm: 0.8; AEC Category: Q200
R26 = CRCW0603100RFKEA: RES, 100, 1%, 0.1 W, 0603; Manufacturer: Vishay-Dale; CompType: Resistor; Value: 100; Value_Code: 100R; Tolerance_%: 1; Power_W: 0.1; Value2: 0.1W; VDC_V: 75; TempCo: 100 ppm/C; EIA_Code: E96; U/M: EA
R27 = CRCW060390K9FKEA: RES, 90.9 k, 1%, 0.1 W, 0603; Manufacturer: Vishay-Dale; CompType: Resistor; Value: 90.9k; Res_ohm: 90900; Value_Code: 90k9; Tolerance_%: 1; Power_W: 0.1; Value2: 0.1W; VDC_V: 75; TempCo: 100 ppm/C; EIA_Code: E96; U/M: EA; SizeArea_mm2: 1.28; SizeX_mm: 1.6; SizeY_mm: 0.8; AEC Category: Q200
R28 = CSR1206FKR200: RES, 0.2, 1%, 0.5 W, 1206; Manufacturer: Stackpole Electronics Inc; CompType: Resistor; Value: 0.2; Value_Code: R200; Tolerance_%: 1; Power_W: 0.5; Value2: 0.5W; TempCo: 100 ppm/C; EIA_Code: E96; U/M: EA; SizeArea_mm2: 5.12; SizeX_mm: 3.2; SizeY_mm: 1.6; SizeZ_mm: 1.35; AEC Category: Q200
R29 = CRCW060347R0JNEA: RES, 47, 5%, 0.1 W, 0603; Manufacturer: Vishay-Dale; CompType: Resistor; Value: 47; Value_Code: 47R0; Tolerance_%: 5; Power_W: 0.1; Value2: 0.1W; VDC_V: 75; TempCo: 200 ppm/C; EIA_Code: E24; U/M: EA
R30 = CRCW0603100KFKEA: RES, 100 k, 1%, 0.1 W, 0603; Manufacturer: Vishay-Dale; CompType: Resistor; Value: 100k; Res_ohm: 100000; Tolerance_%: 1; Power_W: 0.1; Value2: 0.1W; VDC_V: 75; TempCo: 100 ppm/C; EIA_Code: E96; U/M: EA
TP9 TP10 TP12 = 5010: as TP1 on sheet PMP20818_Sh1
TP11 TP16 = 5011: as TP2 on sheet PMP20818_Sh1
TP13-TP15 TP17 = 5012: as TP3 on sheet PMP20818_Sh1
U2 = LM3481MM/NOPB: High Efficiency Low-Side N-Channel Controller for Switching Regulators, 10-pin MSOP, Pb-Free; Manufacturer: Texas Instruments; PackageTopMarking: ZXTT*SJPB; PowerWise: N; CompType: MiscPower
ZX4-ZX6 = AssemblyNote: as ZX1 on sheet PMP20818_Sh1

## Sheet PMP20818_Sh3.SchDoc: LM5141 EVM HARDWARE
size 431 x 279 mm; Date: Not shown in title block; ApprovedBy: Not shown in title block; CheckedBy: Not shown in title block; Author: Not shown in title block; CompanyName: Not shown in title block; Engineer: Not shown in title block; Organization: Not shown in title block; Address1: Not shown in title block; Address2: Not shown in title block; Address3: Not shown in title block; Address4: Not shown in title block; DocumentNumber: 3; Revision: Use project parameter SCH_Rev; SheetNumber: 3; SheetTotal: 3; PageSetup: Record=PageOptions¦CenterHorizontal=True¦CenterVertical=True¦PrintScale=1.00¦XCorrection=1.00¦YCorrection=1.00¦PrintKind=0¦BorderSize=5000000¦LeftOffset=0¦BottomOffset=0¦Orientation=2¦PaperLength=1000¦PaperWidth=1000¦Scale=100¦PaperSource=15¦PrintQuality=600¦MediaType=1¦DitherType=10¦PaperKind=Letter¦PrintScaleMode=1
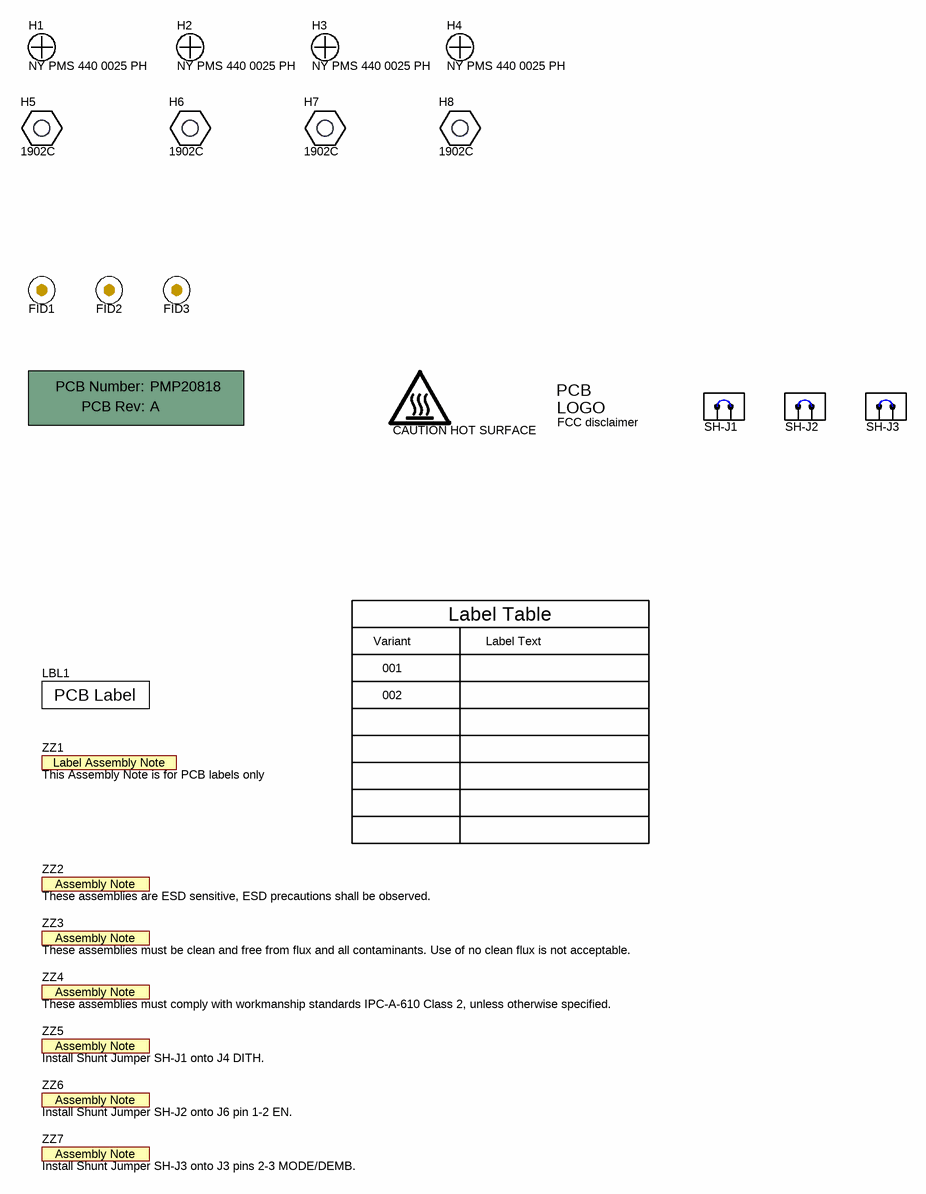
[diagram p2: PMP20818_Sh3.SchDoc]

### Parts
!PCB1  Printed Circuit Board  (value not drawn)  (mechanical)
FID1  Fiducial  [Fiducial10-20]  (value not drawn)
FID2  Fiducial  [Fiducial10-20]  (value not drawn)
FID3  Fiducial  [Fiducial10-20]  (value not drawn)
H1  NY PMS 440 0025 PH  [NY PMS 440 0025 PH]
H2  NY PMS 440 0025 PH  [NY PMS 440 0025 PH]
H3  NY PMS 440 0025 PH  [NY PMS 440 0025 PH]
H4  NY PMS 440 0025 PH  [NY PMS 440 0025 PH]
H5  1902C  [Keystone_1902C]
H6  1902C  [Keystone_1902C]
H7  1902C  [Keystone_1902C]
H8  1902C  [Keystone_1902C]
LBL1  (no value)  [Label_650x200]
Logo1  FCC disclaimer  [FCC_disclaimer]  (no BOM)
Logo2  CAUTION HOT SURFACE  [IEC_HotSurface_Small]  (no BOM)
SH-J1  60900213421  [Wurth_60900213421]  (value not drawn)  (mechanical)
SH-J2  60900213421  [Wurth_60900213421]  (value not drawn)  (mechanical)
SH-J3  60900213421  [Wurth_60900213421]  (value not drawn)  (mechanical)
ZZ1  This Assembly Note is for PCB labels only  [AssemblyNoteLabel]  (no BOM)
ZZ2  These assemblies are ESD sensitive, ESD precautions shall be observed.  [AssemblyNote]  (no BOM)
ZZ3  These assemblies must be clean and free from flux and all contaminants. Use of no clean flux is not acceptable.  [AssemblyNote]  (no BOM)
ZZ4  These assemblies must comply with workmanship standards IPC-A-610 Class 2, unless otherwise specified.  [AssemblyNote]  (no BOM)
ZZ5  Install Shunt Jumper SH-J1 onto J4 DITH.  [AssemblyNote]  (no BOM)
ZZ6  Install Shunt Jumper SH-J2 onto J6 pin 1-2 EN.  [AssemblyNote]  (no BOM)
ZZ7  Install Shunt Jumper SH-J3 onto J3 pins 2-3 MODE/DEMB.  [AssemblyNote]  (no BOM)

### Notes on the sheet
- Variant
- Label Table
- Label Text
- 001
- 002

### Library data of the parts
!PCB1 = PCB: Manufacturer: Any; PartNumber: PMP20818; SymbolCreator: a0412235
FID1-FID3 = Fiducial: Fiducial mark.  There is nothing to buy or mount.; SymbolCreator: codlsc
H1-H4 = NY PMS 440 0025 PH: Machine Screw, Round, #4-40 x 1/4, Nylon, Philips panhead; Manufacturer: B&F Fastener Supply; CompType: Hardware; SymbolCreator: codlsc; U/M: EA
H5-H8 = 1902C: Standoff, Hex, 0.5"L #4-40 Nylon; Manufacturer: Keystone; CompType: Hardware
LBL1 = THT-14-423-10: Thermal Transfer Printable Labels, 0.650" W x 0.200" H - 10,000 per roll; Manufacturer: Brady; SymbolCreator: a0412235; CompType: Label
Logo1 = FCC_disclaimer: SymbolCreator: codlsc
Logo2 = IEC_HotSurface: IEC 61010-1 Hot Surface Warning; SymbolCreator: a0412235
SH-J1-SH-J3 = 60900213421: Shunt, 2.54mm, Gold, Black; Manufacturer: Wurth Elektronik
ZZ1 = AssemblyNoteLabel: SymbolCreator: a0412235
ZZ2-ZZ7 = AssemblyNote: SymbolCreator: codlsc

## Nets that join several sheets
GND: PMP20818_Sh1 (37 pins), PMP20818_Sh2 (22 pins)

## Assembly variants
001: not fitted C18 C19 C22 FID1 FID2 FID3 R3 R5 R13 R21 R22 R23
